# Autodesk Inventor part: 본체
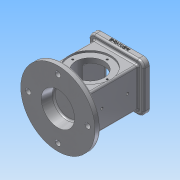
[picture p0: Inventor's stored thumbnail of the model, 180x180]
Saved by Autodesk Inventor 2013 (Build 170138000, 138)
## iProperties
Created: 2018-10
Part Number: 본체
Material: 알루미늄 6061
Document SubType Name: Modeling
Designer: Administrator
Density: 2.71 g/cm^3
Mass: 988.222 g
Surface Area: 743.902 cm^2
Volume: 364.657 cm^3
Author: Administrator
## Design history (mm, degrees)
sketch "스케치1"
  geometry: C1 r 62.5 at (0, 0); 1 further point
  constraints: 1 centre point, 1 coincident
  dimensions: "d0" = 125 diameter of C1
extrude "돌출1" new body sketch "스케치1" distance "d1" = 10; taper "d2" = 0 deg
sketch "스케치2"
  geometry: L1 (-37, -33)-(37, -33); L2 (37, -33)-(37, 33); L3 (37, 33)-(-37, 33); L4 (-37, 33)-(-37, -33); L5 (-37, -33)-(37, 33); L6 (37, -33)-(-37, 33); C1 r 62.5 at (0, 0) reference
  constraints: 12 end point, 2 midpoint, 2 parallel, 1 horizontal, 1 perpendicular
  dimensions: "d3" = 74 distance of L3.end L2.end; "d4" = 66 distance of L2.end L1.end
extrude "돌출2" join sketch "스케치2" distance "d5" = 88; taper "d6" = 0 deg
sketch "스케치4"
  geometry: L1 (-46, -41)-(46, -41); L2 (46, -41)-(46, 41); L3 (46, 41)-(-46, 41); L4 (-46, 41)-(-46, -41); L5 (-46, -41)-(46, 41); L6 (46, -41)-(-46, 41); 1 further point
  constraints: 12 end point, 2 midpoint, 2 parallel, 1 horizontal, 1 perpendicular
  dimensions: "d7" = 92 distance of L3.end L2.end; "d8" = 82 distance of L2.end L1.end
extrude "돌출3" join sketch "스케치4" distance "d9" = 10; taper "d10" = 0 deg
sketch "스케치5"
  geometry: L1 (-26, -26)-(26, -26); L2 (26, -26)-(26, 26); L3 (26, 26)-(-26, 26); L4 (-26, 26)-(-26, -26); L5 (-26, -26)-(26, 26); L6 (26, -26)-(-26, 26); 1 further point
  constraints: 12 end point, 2 midpoint, 2 parallel, 1 horizontal, 1 perpendicular
  dimensions: "d11" = 52 distance of L3.end L2.end; "d12" = 52 distance between parallel lines of L1 L3
extrude "돌출4" cut sketch "스케치5" distance "d13" = 8; taper "d14" = 0 deg
sketch "스케치6"
  geometry: L1 (-22, -22)-(22, -22); L2 (22, -22)-(22, 22); L3 (22, 22)-(-22, 22); L4 (-22, 22)-(-22, -22); L5 (-22, -22)-(22, 22); L6 (22, -22)-(-22, 22); 1 further point
  constraints: 12 end point, 2 midpoint, 2 parallel, 1 horizontal, 1 perpendicular
  dimensions: "d15" = 44 distance of L3.end L2.end; "d16" = 44 distance of L2.end L1.end
extrude "돌출5" cut sketch "스케치6" distance "d17" = 82; taper "d18" = 0 deg
sketch "스케치9"
  geometry: L1 (-25.5, -10)-(99.5, -10) reference; C1 r 35 at (37, 44); 1 further point
  constraints: 1 centre point, 1 vertical alignment
  dimensions: "d19" = 70 diameter of C1; "d20" = 54 distance from line of L1 C1.centre
extrude "돌출6" cut sketch "스케치9" distance "d21" = 3; taper "d22" = 0 deg
fillet "모깎기1" dims "d23" = 3
fillet "모깎기2" dims "d24" = 3
fillet "모깎기3" dims "d25" = 10
fillet "모깎기4" dims "d26" = 3
sketch "스케치10"
  geometry: C1 r 35 at (0, 0) reference; C2 r 24 at (0, 0); 1 further point
  constraints: 1 centre point, 1 coincident
  dimensions: "d27" = 48 diameter of C2
extrude "돌출7" cut sketch "스케치10" distance "d28" = 93.25; taper "d29" = 0 deg
sketch "스케치11"
  geometry: C1 r 62.5 at (0, 0) reference; C2 r 28 at (0, 0)
  constraints: 1 centre point, 1 coincident
  dimensions: "d30" = 56 diameter of C2
extrude "돌출8" cut sketch "스케치11" distance "d31" = 18; taper "d32" = -10 deg
sketch "스케치12"
  geometry: L1 (-32.5, -13)-(92.5, -13) reference; 4 further points
  constraints: 2 vertical alignment, 1 midpoint
  dimensions: "d33" = 43 distance of point (30, 24) point (30, 67); "d35" = 37 distance from line of L1 point (30, 24)
hole "구멍1" sketch "스케치12" at (30, 67), (30, 24) diameter "d36" = 4.134; stored, may be unused: countersink angle "d40" = 90 deg, drill point angle "d42" = 118 deg; dims "d37" = 28, "d38" = 4, "d39" = 2, "d41" = 28
sketch "스케치13"
  geometry: C1 r 24 at (0, 0) reference; 2 further points
  constraints: 1 vertical alignment
  dimensions: "d43" = 29 distance of C1.centre point (0, 29)
hole "구멍2" sketch "스케치13" at (0, 29) diameter "d44" = 3.242; stored, may be unused: countersink angle "d48" = 90 deg, drill point angle "d50" = 118 deg; dims "d45" = 4, "d46" = 4, "d47" = 2, "d49" = 6
sketch "스케치14"
  geometry: A1 r 10 centre (-36, 31) between (-36, 41) and (-46, 31) reference; 2 further points
  constraints: 1 coincident
hole "구멍3" sketch "스케치14" at (-36, 31) diameter "d54" = 3.242; stored, may be unused: countersink angle "d58" = 90 deg, drill point angle "d60" = 118 deg; dims "d55" = 4, "d56" = 4, "d57" = 2, "d59" = 6
sketch "스케치15"
  geometry: C1 r 59.5 at (0, 0) reference; C2 r 4.5 at (0, 50)
  constraints: 1 centre point, 1 vertical alignment
  dimensions: "d67" = 9 diameter of C2; "d69" = 50 distance of C1.centre C2.centre
extrude "돌출9" cut sketch "스케치15" distance "d70" = 18; taper "d71" = 0 deg
fillet "모깎기5" dims "d75" = 3
chamfer "모따기1" distance "d76" = 1; stored, may be unused: second distance "d77" = 2, angle "d78" = 45 deg
sketch "스케치16"
  geometry: L1 (0, 0)-(72, 0) reference; L2 (-10, 0)-(-10, -7) reference; 2 further points
  constraints: 1 other
  dimensions: "d79" = 46 distance from line of L2 point (36, -4); "d80" = 4 distance from line of L1 point (36, -4)
feature "엠보싱1" sketch "스케치16" dims "d81" = 0.5, "d82" = 0
node "솔리드1"
mirror "대칭1"
pattern_circular "원형 패턴1" dims angle "d52" = 360 deg
mirror "대칭2"
pattern_linear "직사각형 패턴1" dims "d63" = 72, "d66" = 62
pattern_circular "원형 패턴2" dims angle "d73" = 360 deg
